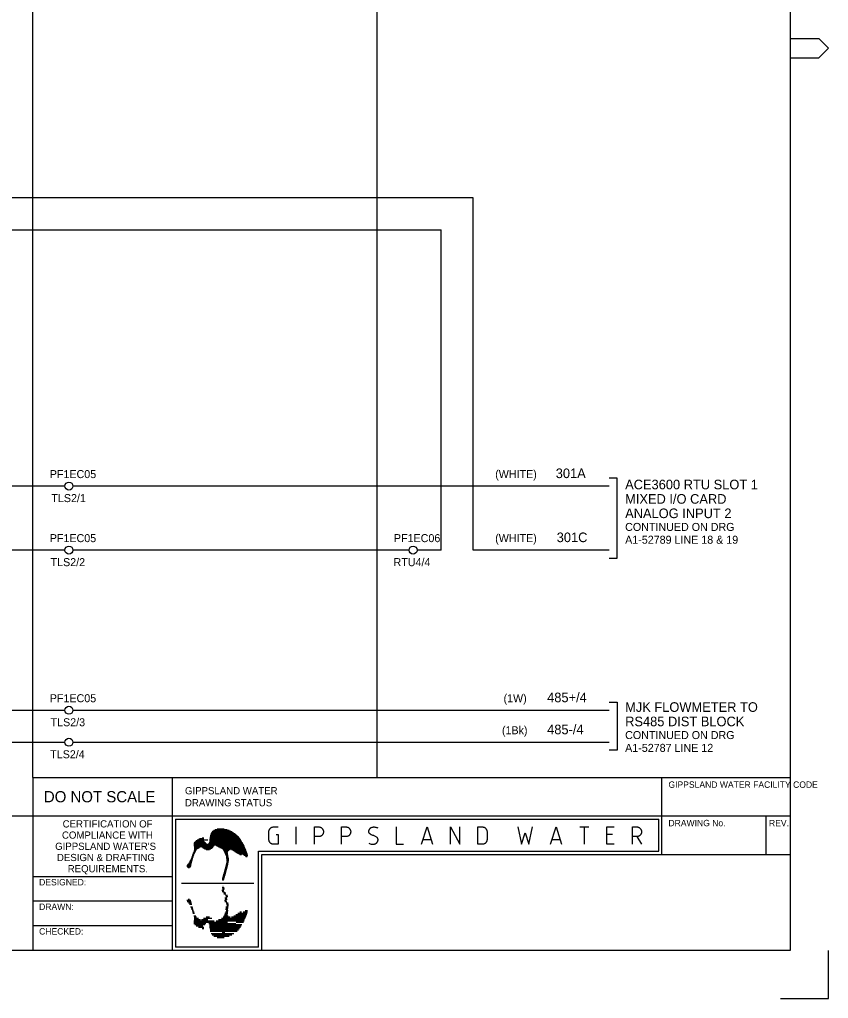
# Model space of a CAD drawing. Extents: x 0 to 841, y 0 to 594.
# Drawn here: x 588.3 to 841, y 0 to 305.7 of the extents above; entities that cross this region are included whole.
import ezdxf

# ---------------------------------------------------------------- set-up
doc = ezdxf.new("R2010")
doc.units = 0
for name, color, linetype in [('A1BORDER', 7, 'Continuous'), ('Level 1', 7, 'Continuous'), ('Level 10', 7, 'Continuous')]:
    doc.layers.add(name, color=color, linetype=linetype)

msp = doc.modelspace()

# ---------------------------------------------------------------- linework, layer by layer
at = {"layer": 'A1BORDER'}
for p, q in [((829, 581), (829, 15)), ((829, 299.76), (838, 299.76)), ((838, 299.76), (841, 296.76)), ((838, 293.76), (841, 296.76)), ((829, 293.76), (838, 293.76)), ((592.5, 69), (592.5, 15)), ((592.5, 69), (829, 69)), ((636, 69), (636, 15)), ((789, 45), (789, 69)), ((28, 57), (829, 57)), ((637, 56), (788, 56)), ((637, 56), (637, 16)), ((788, 46), (788, 56)), ((821.5, 45), (821.5, 57)), ((648.53, 52.12), (654.64, 52.12)), ((648.74, 52.32), (654.24, 52.32)), ((649.02, 52.52), (653.76, 52.52)), ((649.39, 52.72), (653.15, 52.72)), ((650.01, 52.92), (652.2, 52.92)), ((643.04, 48.92), (646.16, 48.92)), ((643.26, 49.12), (645.9, 49.12)), ((643.54, 49.32), (645.57, 49.32)), ((643.85, 49.52), (647.09, 49.52)), ((644.18, 49.72), (645.89, 49.72)), ((644.54, 49.92), (645.36, 49.92)), ((645.37, 50.12), (645.86, 50.12)), ((647.61, 48.92), (657.8, 48.92)), ((647.63, 49.12), (657.68, 49.12)), ((647.66, 49.32), (657.57, 49.32)), ((647.69, 49.52), (657.44, 49.52)), ((647.71, 49.72), (657.31, 49.72)), ((647.75, 49.92), (657.17, 49.92)), ((647.78, 50.12), (657.02, 50.12)), ((647.81, 50.32), (656.86, 50.32)), ((647.85, 50.52), (656.69, 50.52)), ((647.88, 50.72), (656.5, 50.72)), ((647.91, 50.92), (656.3, 50.92)), ((647.96, 51.12), (656.08, 51.12)), ((648.03, 51.32), (655.85, 51.32)), ((648.12, 51.52), (655.59, 51.52)), ((648.23, 51.72), (655.31, 51.72)), ((648.37, 51.92), (655, 51.92)), ((642.72, 45.92), (643.3, 45.92)), ((642.73, 48.12), (658.25, 48.12)), ((642.74, 47.92), (658.35, 47.92)), ((642.75, 48.32), (646.79, 48.32)), ((642.79, 47.72), (649.08, 47.72)), ((642.79, 46.12), (643.4, 46.12)), ((642.81, 48.52), (646.55, 48.52)), ((642.83, 47.52), (648.95, 47.52)), ((642.84, 46.32), (643.5, 46.32)), ((642.85, 47.31), (644.88, 47.31)), ((642.87, 47.12), (644.57, 47.12)), ((642.87, 46.52), (643.6, 46.52)), ((642.88, 46.92), (644.23, 46.92)), ((642.88, 46.72), (643.83, 46.72)), ((642.9, 48.72), (646.37, 48.72)), ((645.14, 47.31), (648.83, 47.31)), ((645.49, 47.12), (648.67, 47.12)), ((645.76, 46.92), (648.42, 46.92)), ((646.05, 46.72), (648.11, 46.72)), ((646.62, 46.52), (647.67, 46.52)), ((647.19, 48.32), (658.14, 48.32)), ((647.42, 48.52), (658.03, 48.52)), ((647.54, 48.72), (657.92, 48.72)), ((649.72, 47.72), (658.45, 47.72)), ((650.12, 47.52), (658.55, 47.52)), ((650.48, 47.31), (658.64, 47.31)), ((650.87, 47.12), (658.73, 47.12)), ((651.36, 46.92), (658.82, 46.92)), ((651.76, 46.72), (658.9, 46.72)), ((651.88, 46.52), (654.15, 46.52)), ((651.99, 46.32), (653.71, 46.32)), ((652.1, 46.12), (653.52, 46.12)), ((652.2, 45.92), (653.4, 45.92)), ((654.57, 46.52), (658.99, 46.52)), ((655, 46.32), (659.07, 46.32)), ((655.31, 46.12), (659.14, 46.12)), ((655.62, 45.92), (659.22, 45.92)), ((663, 46), (788, 46)), ((663, 16), (663, 46)), ((641.55, 42.92), (642.2, 42.92)), ((641.64, 43.12), (642.25, 43.12)), ((641.73, 43.32), (642.3, 43.32)), ((641.82, 43.51), (642.35, 43.51)), ((641.91, 43.72), (642.41, 43.72)), ((641.99, 43.92), (642.48, 43.92)), ((642.06, 44.12), (642.55, 44.12)), ((642.13, 44.32), (642.62, 44.32)), ((642.21, 44.52), (642.69, 44.52)), ((642.28, 44.72), (642.76, 44.72)), ((642.35, 44.92), (642.83, 44.92)), ((642.43, 45.12), (642.9, 45.12)), ((642.5, 45.32), (643, 45.32)), ((642.57, 45.52), (643.1, 45.52)), ((642.65, 45.72), (643.2, 45.72)), ((652.31, 45.72), (653.33, 45.72)), ((652.41, 45.52), (653.31, 45.52)), ((652.5, 45.32), (653.34, 45.32)), ((652.6, 45.12), (653.38, 45.12)), ((652.69, 44.92), (653.41, 44.92)), ((652.78, 44.72), (653.44, 44.72)), ((652.83, 44.52), (653.48, 44.52)), ((652.86, 44.32), (653.53, 44.32)), ((652.89, 44.12), (653.57, 44.12)), ((652.91, 43.92), (653.62, 43.92)), ((652.94, 43.72), (653.67, 43.72)), ((652.97, 43.51), (653.71, 43.51)), ((653, 43.32), (653.69, 43.32)), ((653.02, 43.12), (653.67, 43.12)), ((653.05, 42.92), (653.64, 42.92)), ((655.93, 45.72), (659.29, 45.72)), ((656.24, 45.52), (659.35, 45.52)), ((656.55, 45.32), (659.42, 45.32)), ((656.86, 45.12), (657.74, 45.12)), ((657.17, 44.92), (657.68, 44.92)), ((657.51, 44.72), (657.54, 44.72)), ((657.91, 45.12), (659.48, 45.12)), ((658.19, 44.92), (659.54, 44.92)), ((658.47, 44.72), (659.59, 44.72)), ((658.75, 44.52), (659.58, 44.52)), ((659.02, 44.32), (659.47, 44.32)), ((664, 45), (829, 45)), ((664, 15), (664, 45)), ((640.62, 41.32), (641.88, 41.32)), ((640.63, 41.52), (641.93, 41.52)), ((640.72, 41.12), (641.73, 41.12)), ((640.73, 41.72), (641.95, 41.72)), ((640.9, 41.92), (641.97, 41.92)), ((641.03, 40.92), (641.43, 40.92)), ((641.1, 42.12), (642, 42.12)), ((641.25, 42.31), (642.04, 42.31)), ((641.37, 42.52), (642.09, 42.52)), ((641.46, 42.72), (642.15, 42.72)), ((652.3, 39.92), (652.93, 39.92)), ((652.36, 40.12), (652.99, 40.12)), ((652.41, 40.32), (653.04, 40.32)), ((652.47, 40.52), (653.1, 40.52)), ((652.52, 40.72), (653.15, 40.72)), ((652.57, 40.92), (653.2, 40.92)), ((652.63, 41.12), (653.26, 41.12)), ((652.68, 41.32), (653.31, 41.32)), ((652.74, 41.52), (653.37, 41.52)), ((652.79, 41.72), (653.41, 41.72)), ((652.85, 41.92), (653.45, 41.92)), ((652.9, 42.12), (653.49, 42.12)), ((652.95, 42.31), (653.53, 42.31)), ((652.99, 42.52), (653.57, 42.52)), ((653.03, 42.72), (653.61, 42.72)), ((636, 38), (592.5, 38)), ((651.63, 37.32), (652.23, 37.32)), ((651.64, 37.12), (652.17, 37.12)), ((651.65, 37.52), (652.28, 37.52)), ((651.71, 37.72), (652.34, 37.72)), ((651.76, 37.92), (652.39, 37.92)), ((651.79, 36.92), (651.9, 36.92)), ((651.82, 38.12), (652.44, 38.12)), ((651.87, 38.32), (652.5, 38.32)), ((651.92, 38.52), (652.55, 38.52)), ((651.98, 38.72), (652.61, 38.72)), ((652.03, 38.92), (652.66, 38.92)), ((652.09, 39.12), (652.72, 39.12)), ((652.14, 39.32), (652.77, 39.32)), ((652.2, 39.52), (652.82, 39.52)), ((652.25, 39.72), (652.88, 39.72)), ((638.93, 35.98), (661.47, 35.98)), ((651.54, 33.84), (652.17, 33.84)), ((651.63, 34.64), (652.23, 34.64)), ((651.71, 34.24), (652.34, 34.24)), ((651.79, 35.04), (651.9, 35.04)), ((640.62, 30.64), (641.88, 30.64)), ((641.03, 31.04), (641.43, 31.04)), ((651.65, 33.44), (652.28, 33.44)), ((652.03, 33.04), (652.66, 33.04)), ((652.14, 32.64), (652.77, 32.64)), ((652.34, 30.64), (652.97, 30.64)), ((652.47, 31.44), (653.1, 31.44)), ((652.57, 31.04), (653.2, 31.04)), ((652.66, 32.24), (653.29, 32.24)), ((652.77, 31.84), (653.4, 31.84)), ((636, 30.34), (592.5, 30.34)), ((640.73, 30.24), (641.95, 30.24)), ((641.1, 29.84), (642, 29.84)), ((641.37, 29.44), (642.09, 29.44)), ((641.73, 28.64), (642.3, 28.64)), ((641.91, 28.24), (642.41, 28.24)), ((642.06, 27.84), (642.55, 27.84)), ((652.45, 30.24), (653.07, 30.24)), ((652.66, 27.84), (653.35, 27.84)), ((652.72, 28.24), (653.44, 28.24)), ((652.77, 28.64), (653.46, 28.64)), ((652.9, 29.84), (653.49, 29.84)), ((652.99, 29.44), (653.57, 29.44)), ((653.05, 29.04), (653.64, 29.04)), ((642.21, 27.44), (642.69, 27.44)), ((642.35, 27.04), (642.83, 27.04)), ((642.5, 26.64), (643, 26.64)), ((642.79, 25.84), (643.4, 25.84)), ((642.85, 24.65), (644.88, 24.65)), ((642.87, 25.44), (643.6, 25.44)), ((642.88, 25.04), (644.23, 25.04)), ((645.14, 24.65), (647.18, 24.65)), ((645.76, 25.04), (648.42, 25.04)), ((646.62, 25.44), (647.67, 25.44)), ((650.48, 24.65), (658.64, 24.65)), ((651.36, 25.04), (658.82, 25.04)), ((651.88, 25.44), (654.15, 25.44)), ((652.1, 25.84), (653.52, 25.84)), ((652.31, 26.24), (653.33, 26.24)), ((652.5, 26.64), (653.34, 26.64)), ((652.69, 27.04), (653.41, 27.04)), ((652.83, 27.44), (653.48, 27.44)), ((654.57, 25.44), (658.99, 25.44)), ((655.31, 25.84), (659.14, 25.84)), ((655.93, 26.24), (659.29, 26.24)), ((656.55, 26.64), (659.42, 26.64)), ((657.17, 27.04), (657.68, 27.04)), ((658.19, 27.04), (659.54, 27.04)), ((658.75, 27.44), (659.58, 27.44)), ((636, 22.67), (592.5, 22.67)), ((642.73, 23.84), (653.27, 23.84)), ((642.79, 24.24), (649.08, 24.24)), ((642.81, 23.44), (646.55, 23.44)), ((643.04, 23.04), (646.16, 23.04)), ((643.54, 22.64), (645.57, 22.64)), ((644.18, 22.24), (645.89, 22.24)), ((645.37, 21.84), (645.86, 21.84)), ((647.42, 23.44), (655.89, 23.44)), ((647.61, 23.04), (657.8, 23.04)), ((647.66, 22.64), (657.57, 22.64)), ((647.71, 22.24), (657.31, 22.24)), ((647.78, 21.84), (657.02, 21.84)), ((647.85, 21.44), (656.69, 21.44)), ((649.72, 24.24), (658.45, 24.24)), ((655.94, 23.84), (658.25, 23.84)), ((647.91, 21.04), (656.3, 21.04)), ((648.23, 20.24), (655.31, 20.24)), ((648.53, 19.84), (654.64, 19.84)), ((649.02, 19.44), (653.76, 19.44)), ((650.01, 19.04), (652.2, 19.04)), ((651.57, 20.64), (652.44, 20.64)), ((663, 16), (637, 16)), ((829, 15), (28, 15)), ((829, 15), (829, 15)), ((841, 0), (841, 15)), ((826, 0), (841, 0))]:
    msp.add_line(p, q, dxfattribs=at)
for points in [[(668.49, 51.15), (669.06, 51.15), (669.06, 48.16), (667.64, 48.16), (667.51, 48.16), (667.39, 48.18), (667.28, 48.21), (667.15, 48.25), (667.04, 48.3), (666.93, 48.36), (666.82, 48.43), (666.73, 48.51), (666.64, 48.6), (666.55, 48.7), (666.48, 48.8), (666.41, 48.91), (666.35, 49.02), (666.31, 49.14), (666.27, 49.27), (666.24, 49.39), (666.22, 49.52), (666.22, 49.66), (666.22, 52.05), (666.22, 52.18), (666.24, 52.31), (666.27, 52.43), (666.31, 52.56), (666.35, 52.67), (666.41, 52.79), (666.48, 52.9), (666.55, 53), (666.64, 53.1), (666.73, 53.19), (666.82, 53.27), (666.93, 53.34), (667.04, 53.4), (667.15, 53.45), (667.28, 53.49), (667.39, 53.52), (667.51, 53.54), (667.64, 53.54), (669.06, 53.54)], [(674.74, 48.16), (674.74, 53.54)], [(680.42, 48.16), (680.42, 53.54), (681.84, 53.54), (681.96, 53.54), (682.08, 53.52), (682.2, 53.49), (682.32, 53.45), (682.43, 53.4), (682.54, 53.34), (682.65, 53.27), (682.74, 53.19), (682.84, 53.1), (682.92, 53), (682.99, 52.9), (683.06, 52.79), (683.12, 52.67), (683.17, 52.56), (683.21, 52.43), (683.23, 52.31), (683.25, 52.18), (683.26, 52.05), (683.25, 51.91), (683.23, 51.78), (683.21, 51.66), (683.17, 51.53), (683.12, 51.42), (683.06, 51.3), (682.99, 51.19), (682.92, 51.09), (682.84, 50.99), (682.74, 50.9), (682.65, 50.82), (682.54, 50.75), (682.43, 50.69), (682.32, 50.64), (682.2, 50.6), (682.08, 50.57), (681.96, 50.55), (681.84, 50.55), (680.42, 50.55)], [(688.93, 48.16), (688.93, 53.54), (690.35, 53.54), (690.47, 53.54), (690.59, 53.52), (690.71, 53.49), (690.83, 53.45), (690.94, 53.4), (691.05, 53.34), (691.16, 53.27), (691.26, 53.19), (691.35, 53.1), (691.43, 53), (691.51, 52.9), (691.57, 52.79), (691.63, 52.67), (691.68, 52.56), (691.72, 52.43), (691.75, 52.31), (691.76, 52.18), (691.77, 52.05), (691.76, 51.91), (691.75, 51.78), (691.72, 51.66), (691.68, 51.53), (691.63, 51.42), (691.57, 51.3), (691.51, 51.19), (691.43, 51.09), (691.35, 50.99), (691.26, 50.9), (691.16, 50.82), (691.05, 50.75), (690.94, 50.69), (690.83, 50.64), (690.71, 50.6), (690.59, 50.57), (690.47, 50.55), (690.35, 50.55), (688.93, 50.55)], [(697.45, 48.46), (697.67, 48.36), (697.9, 48.27), (698.12, 48.21), (698.36, 48.17), (698.6, 48.16), (698.84, 48.16), (698.87, 48.16), (699.03, 48.18), (699.18, 48.21), (699.33, 48.26), (699.48, 48.32), (699.62, 48.4), (699.72, 48.46), (699.81, 48.53), (699.9, 48.61), (699.98, 48.69), (700.05, 48.78), (700.11, 48.88), (700.17, 48.99), (700.22, 49.09), (700.25, 49.21), (700.28, 49.32), (700.29, 49.36), (700.3, 49.44), (700.3, 49.52), (700.3, 49.61), (700.29, 49.69), (700.27, 49.77), (700.25, 49.86), (700.22, 49.93), (700.18, 50.01), (700.14, 50.09), (700.09, 50.15), (700.04, 50.21), (700.01, 50.25), (699.85, 50.39), (699.69, 50.51), (699.52, 50.61), (699.34, 50.7), (699.15, 50.78), (698.95, 50.83), (698.87, 50.85), (698.68, 50.9), (698.49, 50.96), (698.3, 51.04), (698.12, 51.14), (697.96, 51.26), (697.8, 51.39), (697.73, 51.45), (697.67, 51.51), (697.62, 51.57), (697.58, 51.64), (697.53, 51.71), (697.5, 51.79), (697.47, 51.87), (697.46, 51.95), (697.44, 52.04), (697.43, 52.12), (697.43, 52.21), (697.44, 52.29), (697.45, 52.35), (697.47, 52.46), (697.51, 52.58), (697.55, 52.69), (697.61, 52.79), (697.67, 52.89), (697.74, 52.99), (697.82, 53.07), (697.9, 53.15), (697.99, 53.23), (698.02, 53.24), (698.15, 53.33), (698.3, 53.4), (698.44, 53.45), (698.6, 53.5), (698.75, 53.52), (698.87, 53.54), (699.11, 53.55), (699.35, 53.53), (699.58, 53.49), (699.82, 53.43), (700.04, 53.35), (700.27, 53.25)], [(705.96, 53.54), (705.96, 48.16), (708.23, 48.16)], [(713.91, 48.16), (715.61, 53.54), (717.32, 48.16)], [(722.99, 48.16), (722.99, 53.54), (725.83, 48.16), (725.83, 53.54)], [(731.52, 48.16), (731.52, 53.54), (732.94, 53.54), (733.06, 53.54), (733.18, 53.52), (733.3, 53.49), (733.42, 53.45), (733.53, 53.4), (733.64, 53.34), (733.75, 53.27), (733.84, 53.19), (733.94, 53.1), (734.02, 53), (734.09, 52.9), (734.16, 52.79), (734.22, 52.67), (734.27, 52.56), (734.31, 52.43), (734.33, 52.31), (734.35, 52.18), (734.36, 52.05), (734.36, 49.66), (734.35, 49.52), (734.33, 49.39), (734.31, 49.27), (734.27, 49.14), (734.22, 49.02), (734.16, 48.91), (734.09, 48.8), (734.02, 48.7), (733.94, 48.6), (733.84, 48.51), (733.75, 48.43), (733.64, 48.36), (733.53, 48.3), (733.42, 48.25), (733.3, 48.21), (733.18, 48.18), (733.06, 48.16), (732.94, 48.16), (731.52, 48.16)], [(744.01, 53.54), (745.14, 48.16), (746.28, 51.75), (747.41, 48.16), (748.55, 53.54)], [(754.22, 48.16), (755.92, 53.54), (757.63, 48.16)], [(763.31, 53.54), (766.15, 53.54)], [(764.73, 53.54), (764.73, 48.16)], [(774.09, 48.16), (771.82, 48.16), (771.82, 53.54), (774.09, 53.54)], [(779.78, 48.16), (779.78, 53.54), (781.2, 53.54), (781.32, 53.54), (781.44, 53.52), (781.56, 53.49), (781.68, 53.45), (781.79, 53.4), (781.9, 53.34), (782.01, 53.27), (782.1, 53.19), (782.2, 53.1), (782.28, 53), (782.35, 52.9), (782.42, 52.79), (782.48, 52.67), (782.53, 52.56), (782.56, 52.43), (782.59, 52.31), (782.61, 52.18), (782.61, 52.05), (782.61, 51.91), (782.59, 51.78), (782.56, 51.66), (782.53, 51.53), (782.48, 51.42), (782.42, 51.3), (782.35, 51.19), (782.28, 51.09), (782.2, 50.99), (782.1, 50.9), (782.01, 50.82), (781.9, 50.75), (781.79, 50.69), (781.68, 50.64), (781.56, 50.6), (781.44, 50.57), (781.32, 50.55), (781.2, 50.55), (779.78, 50.55)], [(714.48, 49.66), (716.75, 49.66)], [(754.79, 49.66), (757.06, 49.66)], [(773.53, 51.15), (771.82, 51.15)], [(781.2, 50.55), (782.61, 48.16)]]:
    msp.add_lwpolyline(points, dxfattribs=at)
at = {"layer": 'Level 1'}
for p, q in [((592.5, 69), (592.5, 572.5)), ((700, 69), (700, 572.5)), ((730, 250), (525, 250)), ((730, 140), (730, 250)), ((525, 240), (720, 240)), ((720, 140), (720, 240)), ((602.5, 160), (315, 160)), ((602.5, 160), (602.5, 160)), ((772.5, 160), (605, 160)), ((605, 160), (605, 160)), ((602.5, 140), (315, 140)), ((602.5, 140), (602.5, 140)), ((710, 140), (605, 140)), ((605, 140), (605, 140)), ((710, 140), (710, 140)), ((712.5, 140), (712.5, 140)), ((720, 140), (712.5, 140)), ((772.5, 140), (730, 140)), ((315, 90), (602.5, 90)), ((602.5, 90), (602.5, 90)), ((605, 90), (605, 90)), ((605, 90), (772.5, 90)), ((315, 80), (602.5, 80)), ((602.5, 80), (602.5, 80)), ((605, 80), (605, 80)), ((605, 80), (772.5, 80))]:
    msp.add_line(p, q, dxfattribs=at)
for points in [[(772.5, 137.5), (775, 137.5), (775, 162.5), (772.5, 162.5)], [(772.5, 92.5), (775, 92.5), (775, 77.5), (772.5, 77.5)]]:
    msp.add_lwpolyline(points, dxfattribs=at)
at = {"layer": 'Level 10'}
for centre in [(603.75, 160), (603.75, 140), (711.25, 140), (603.75, 90), (603.75, 80)]:
    msp.add_circle(centre, 1.25, dxfattribs=at)

# ---------------------------------------------------------------- texts
at = {"layer": 'A1BORDER'}
for s, height, p in [('GIPPSLAND WATER FACILITY CODE', 2, (791.03, 65.77)), ('DO NOT SCALE', 3.5, (595.92, 61.25)), ('GIPPSLAND WATER', 2.25, (640, 63.75)), ('DRAWING STATUS', 2.25, (640, 60)), ('CERTIFICATION OF', 2.25, (601.79, 53.39)), ('DRAWING No.', 2, (791.03, 53.77)), ('REV.', 2, (822.43, 53.77)), ('COMPLIANCE WITH', 2.25, (601.57, 49.89)), ("GIPPSLAND WATER'S", 2.25, (599.45, 46.39)), ('DESIGN & DRAFTING', 2.25, (600, 42.89)), ('REQUIREMENTS.', 2.25, (603.37, 39.39)), ('DESIGNED:', 2, (594.44, 35.29)), ('DRAWN:', 2, (594.44, 27.62)), ('CHECKED:', 2, (594.44, 19.95))]:
    msp.add_text(s, height=height, dxfattribs=at).set_placement(p)
at = {"layer": 'Level 1'}
for s, height, p in [('(WHITE)', 2.5, (736.9, 162.5)), ('301A', 3, (755.82, 162.5)), ('PF1EC05', 2.5, (597.77, 162.5)), ('ACE3600 RTU SLOT 1', 3, (777.5, 159)), ('TLS2/1', 2.5, (598.27, 155)), ('MIXED I/O CARD', 3, (777.5, 154.5)), ('ANALOG INPUT 2', 3, (777.5, 150)), ('CONTINUED ON DRG', 2.5, (777.5, 146)), ('PF1EC05', 2.5, (597.77, 142.5)), ('PF1EC06', 2.5, (705.27, 142.5)), ('(WHITE)', 2.5, (736.9, 142.5)), ('301C', 3, (756.12, 142.5)), ('A1-52789 LINE 18 & 19', 2.5, (777.5, 142)), ('TLS2/2', 2.5, (598.02, 135)), ('RTU4/4', 2.5, (705.15, 135)), ('PF1EC05', 2.5, (597.77, 92.5)), ('(1W)', 2.5, (739.51, 92.5)), ('485+/4', 3, (753.13, 92.5)), ('MJK FLOWMETER TO', 3, (777.5, 89.5)), ('TLS2/3', 2.5, (598.02, 85)), ('485-/4', 3, (753.13, 82.5)), ('RS485 DIST BLOCK', 3, (777.5, 85)), ('(1Bk)', 2.5, (739.01, 82.5)), ('CONTINUED ON DRG', 2.5, (777.5, 81)), ('A1-52787 LINE 12', 2.5, (777.5, 77)), ('TLS2/4', 2.5, (597.9, 75))]:
    msp.add_text(s, height=height, dxfattribs=at).set_placement(p)

doc.saveas('drawing.dxf')
